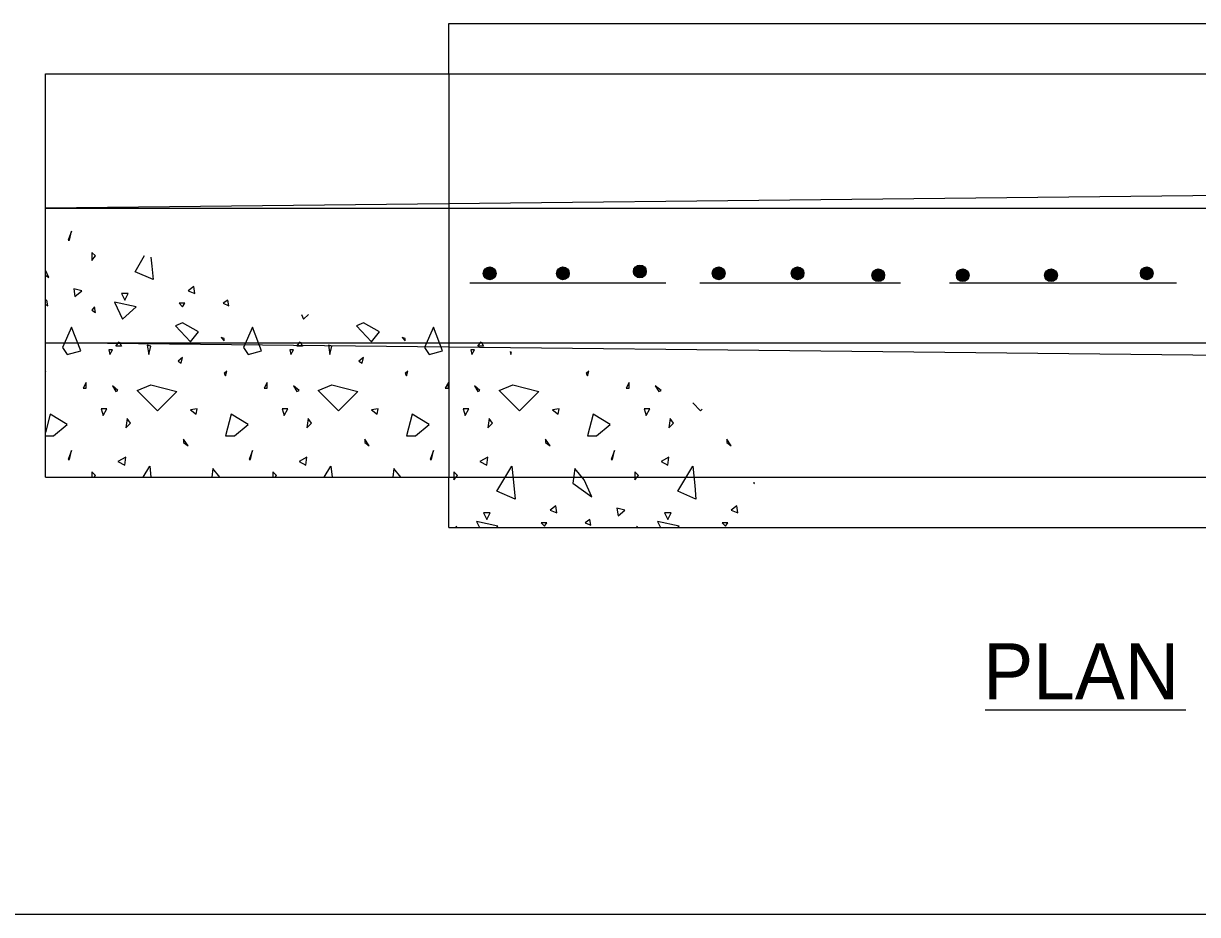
# Model space of a CAD drawing. Extents: x -0.8 to 6.5, y 10.6 to 20.8.
# Drawn here: x 2.206 to 4.302, y 19.16 to 20.751 of the extents above; entities that cross this region are included whole.
import ezdxf

# ---------------------------------------------------------------- set-up
doc = ezdxf.new("R2010")
doc.units = 0
for name, color, linetype in [('DETL-DIMS', 7, 'Continuous'), ('DETL-LINE', 7, 'Continuous'), ('DETL-PATT', 7, 'Continuous'), ('DETL-TITL', 7, 'Continuous')]:
    doc.layers.add(name, color=color, linetype=linetype)

msp = doc.modelspace()

# ---------------------------------------------------------------- linework, layer by layer
at = {"layer": 'DETL-DIMS'}
msp.add_line((5.9505, 19.1603), (0.6594, 19.1603), dxfattribs=at)
at = {"layer": 'DETL-LINE'}
for p, q in [((2.9657, 20.6609), (2.9657, 20.7509)), ((2.9657, 20.7509), (5.3675, 20.7509)), ((2.2458, 19.9408), (2.2458, 20.6609)), ((2.2458, 20.6609), (5.3658, 20.6609)), ((2.9657, 20.6609), (2.9657, 19.9408)), ((5.0074, 20.4509), (2.2458, 20.4209)), ((2.2458, 20.4209), (5.0074, 20.4209)), ((3.003, 20.2881), (3.3531, 20.2881)), ((3.4135, 20.2881), (3.7719, 20.2881)), ((3.8591, 20.2881), (4.2645, 20.2881)), ((2.2458, 20.181), (5.0074, 20.181)), ((5.0074, 20.151), (2.2458, 20.181)), ((2.2458, 19.9408), (5.3658, 19.9408)), ((2.9657, 19.8509), (2.9657, 19.9408)), ((2.9657, 19.8509), (5.3675, 19.8509))]:
    msp.add_line(p, q, dxfattribs=at)
for centre, radius in [((3.0385, 20.3048), 0.0114), ((3.0384, 20.3049), 0.0107), ((3.0373, 20.3049), 0.00926), ((3.0385, 20.3047), 0.0103), ((3.0388, 20.3042), 0.0101), ((3.0388, 20.3045), 0.0094), ((3.039, 20.3045), 0.00889), ((3.0377, 20.3054), 0.00766), ((3.0391, 20.3042), 0.00843), ((3.0375, 20.3045), 0.00665), ((3.0392, 20.3041), 0.00805), ((3.0391, 20.3039), 0.00767), ((3.037, 20.3041), 0.00531), ((3.0393, 20.3039), 0.00747), ((3.0391, 20.304), 0.00722), ((3.0395, 20.3038), 0.0069), ((3.0395, 20.304), 0.00646), ((3.0396, 20.304), 0.00601), ((3.0379, 20.3043), 0.00429), ((3.0396, 20.3042), 0.00551), ((3.0397, 20.304), 0.00519), ((3.0397, 20.304), 0.00468), ((3.0399, 20.3036), 0.00448), ((3.04, 20.3035), 0.00409), ((3.04, 20.3036), 0.00358), ((3.0401, 20.3037), 0.00346), ((3.0401, 20.3034), 0.00319), ((3.0402, 20.3036), 0.00306), ((3.0403, 20.3036), 0.00262), ((3.0401, 20.3038), 0.00218), ((3.0404, 20.3035), 0.00194), ((3.0404, 20.3035), 0.00161), ((3.0406, 20.3034), 0.00123), ((3.0406, 20.3036), 0.00108), ((3.0409, 20.3035), 0.00136), ((3.0405, 20.3036), 0.000706), ((3.1692, 20.3048), 0.0114), ((3.1691, 20.3049), 0.0107), ((3.168, 20.3049), 0.00926), ((3.1692, 20.3047), 0.0103), ((3.1695, 20.3042), 0.0101), ((3.1694, 20.3045), 0.0094), ((3.1684, 20.3054), 0.00766), ((3.1697, 20.3045), 0.00889), ((3.1698, 20.3042), 0.00843), ((3.1682, 20.3045), 0.00665), ((3.1699, 20.3041), 0.00805), ((3.1698, 20.3039), 0.00767), ((3.1677, 20.3041), 0.00531), ((3.17, 20.3039), 0.00747), ((3.1698, 20.304), 0.00722), ((3.1701, 20.3038), 0.0069), ((3.1702, 20.304), 0.00646), ((3.1703, 20.304), 0.00601), ((3.1685, 20.3043), 0.00429), ((3.1703, 20.3042), 0.00551), ((3.1703, 20.304), 0.00519), ((3.1703, 20.304), 0.00468), ((3.1705, 20.3036), 0.00448), ((3.1706, 20.3035), 0.00409), ((3.1706, 20.3036), 0.00358), ((3.1708, 20.3037), 0.00346), ((3.1708, 20.3034), 0.00319), ((3.1709, 20.3036), 0.00306), ((3.171, 20.3036), 0.00262), ((3.1708, 20.3038), 0.00218), ((3.171, 20.3035), 0.00194), ((3.1711, 20.3035), 0.00161), ((3.1712, 20.3034), 0.00123), ((3.1712, 20.3036), 0.00108), ((3.1716, 20.3035), 0.00136), ((3.1712, 20.3036), 0.000706), ((3.3065, 20.3082), 0.0114), ((3.3064, 20.3083), 0.0107), ((3.3054, 20.3083), 0.00926), ((3.3065, 20.308), 0.0103), ((3.3068, 20.3075), 0.0101), ((3.3068, 20.3079), 0.0094), ((3.3058, 20.3087), 0.00766), ((3.307, 20.3078), 0.00889), ((3.3071, 20.3076), 0.00843), ((3.3056, 20.3078), 0.00665), ((3.3072, 20.3075), 0.00805), ((3.3071, 20.3073), 0.00767), ((3.305, 20.3075), 0.00531), ((3.3073, 20.3073), 0.00747), ((3.3072, 20.3074), 0.00722), ((3.3075, 20.3072), 0.0069), ((3.3076, 20.3073), 0.00646), ((3.3076, 20.3074), 0.00601), ((3.3059, 20.3077), 0.00429), ((3.3076, 20.3075), 0.00551), ((3.3077, 20.3074), 0.00519), ((3.3077, 20.3073), 0.00468), ((3.3079, 20.3069), 0.00448), ((3.308, 20.3069), 0.00409), ((3.308, 20.307), 0.00358), ((3.3081, 20.3071), 0.00346), ((3.3081, 20.3068), 0.00319), ((3.3083, 20.307), 0.00306), ((3.3083, 20.3069), 0.00262), ((3.3081, 20.3071), 0.00218), ((3.3084, 20.3069), 0.00194), ((3.3085, 20.3069), 0.00161), ((3.3086, 20.3068), 0.00123), ((3.3086, 20.3069), 0.00108), ((3.309, 20.3069), 0.00136), ((3.3086, 20.3069), 0.000706), ((3.3084, 20.3069), 0.000332), ((3.3087, 20.3069), 0.000211), ((3.4472, 20.3049), 0.0114), ((3.4471, 20.305), 0.0107), ((3.4461, 20.305), 0.00926), ((3.4473, 20.3047), 0.0103), ((3.4476, 20.3042), 0.0101), ((3.4475, 20.3046), 0.0094), ((3.4465, 20.3054), 0.00766), ((3.4478, 20.3045), 0.00889), ((3.4478, 20.3043), 0.00843), ((3.4463, 20.3045), 0.00665), ((3.448, 20.3041), 0.00805), ((3.4478, 20.3039), 0.00767), ((3.4457, 20.3041), 0.00531), ((3.448, 20.3039), 0.00747), ((3.4479, 20.3041), 0.00722), ((3.4482, 20.3039), 0.0069), ((3.4483, 20.304), 0.00646), ((3.4483, 20.3041), 0.00601), ((3.4466, 20.3044), 0.00429), ((3.4483, 20.3042), 0.00551), ((3.4484, 20.3041), 0.00519), ((3.4484, 20.304), 0.00468), ((3.4486, 20.3036), 0.00448), ((3.4487, 20.3036), 0.00409), ((3.4487, 20.3037), 0.00358), ((3.4489, 20.3038), 0.00346), ((3.4489, 20.3034), 0.00319), ((3.449, 20.3037), 0.00306), ((3.449, 20.3036), 0.00262), ((3.4489, 20.3038), 0.00218), ((3.4491, 20.3035), 0.00194), ((3.4492, 20.3036), 0.00161), ((3.4493, 20.3035), 0.00123), ((3.4493, 20.3036), 0.00108), ((3.4497, 20.3036), 0.00136), ((3.4493, 20.3036), 0.000706), ((3.588, 20.3049), 0.0114), ((3.5879, 20.305), 0.0107), ((3.5868, 20.305), 0.00926), ((3.588, 20.3047), 0.0103), ((3.5883, 20.3042), 0.0101), ((3.5882, 20.3046), 0.0094), ((3.5872, 20.3054), 0.00766), ((3.5885, 20.3045), 0.00889), ((3.5886, 20.3043), 0.00843), ((3.587, 20.3045), 0.00665), ((3.5887, 20.3041), 0.00805), ((3.5886, 20.3039), 0.00767), ((3.5865, 20.3041), 0.00531), ((3.5888, 20.3039), 0.00747), ((3.5886, 20.3041), 0.00722), ((3.5889, 20.3039), 0.0069), ((3.589, 20.304), 0.00646), ((3.5873, 20.3044), 0.00429), ((3.5891, 20.3041), 0.00601), ((3.5891, 20.3042), 0.00551), ((3.5891, 20.3041), 0.00519), ((3.5891, 20.304), 0.00468), ((3.5893, 20.3036), 0.00448), ((3.5894, 20.3036), 0.00409), ((3.5894, 20.3037), 0.00358), ((3.5896, 20.3038), 0.00346), ((3.5896, 20.3034), 0.00319), ((3.5897, 20.3037), 0.00306), ((3.5898, 20.3036), 0.00262), ((3.5896, 20.3038), 0.00218), ((3.5898, 20.3035), 0.00194), ((3.5899, 20.3036), 0.00161), ((3.59, 20.3035), 0.00123), ((3.59, 20.3036), 0.00108), ((3.5904, 20.3036), 0.00136), ((3.59, 20.3036), 0.000706), ((3.732, 20.3015), 0.0114), ((3.7319, 20.3016), 0.0107), ((3.7309, 20.3016), 0.00926), ((3.7321, 20.3013), 0.0103), ((3.7324, 20.3008), 0.0101), ((3.7323, 20.3012), 0.0094), ((3.7313, 20.3021), 0.00766), ((3.7326, 20.3012), 0.00889), ((3.7326, 20.3009), 0.00843), ((3.7311, 20.3012), 0.00665), ((3.7328, 20.3008), 0.00805), ((3.7326, 20.3006), 0.00767), ((3.7305, 20.3008), 0.00531), ((3.7328, 20.3006), 0.00747), ((3.7327, 20.3007), 0.00722), ((3.733, 20.3005), 0.0069), ((3.7331, 20.3006), 0.00646), ((3.7331, 20.3007), 0.00601), ((3.7314, 20.301), 0.00429), ((3.7331, 20.3008), 0.00551), ((3.7332, 20.3007), 0.00519), ((3.7332, 20.3006), 0.00468), ((3.7334, 20.3003), 0.00448), ((3.7335, 20.3002), 0.00409), ((3.8828, 20.3015), 0.0114), ((3.8827, 20.3016), 0.0107), ((3.8817, 20.3016), 0.00926), ((3.8829, 20.3013), 0.0103), ((3.8832, 20.3008), 0.0101), ((3.8831, 20.3012), 0.0094), ((3.8821, 20.3021), 0.00766), ((3.8834, 20.3012), 0.00889), ((3.8834, 20.3009), 0.00843), ((3.8819, 20.3012), 0.00665), ((3.8836, 20.3008), 0.00805), ((3.8834, 20.3006), 0.00767), ((3.8813, 20.3008), 0.00531), ((3.8836, 20.3006), 0.00747), ((3.8835, 20.3007), 0.00722), ((3.8838, 20.3005), 0.0069), ((3.8839, 20.3006), 0.00646), ((3.8839, 20.3007), 0.00601), ((3.8822, 20.301), 0.00429), ((3.8839, 20.3008), 0.00551), ((3.884, 20.3007), 0.00519), ((3.884, 20.3006), 0.00468), ((3.8842, 20.3003), 0.00448), ((3.8843, 20.3002), 0.00409), ((4.0403, 20.3015), 0.0114), ((4.0402, 20.3016), 0.0107), ((4.0392, 20.3016), 0.00926), ((4.0403, 20.3013), 0.0103), ((4.0406, 20.3008), 0.0101), ((4.0406, 20.3012), 0.0094), ((4.0396, 20.3021), 0.00766), ((4.0408, 20.3012), 0.00889), ((4.0409, 20.3009), 0.00843), ((4.0394, 20.3012), 0.00665), ((4.041, 20.3008), 0.00805), ((4.0409, 20.3006), 0.00767), ((4.0388, 20.3008), 0.00531), ((4.0411, 20.3006), 0.00747), ((4.041, 20.3007), 0.00722), ((4.0413, 20.3005), 0.0069), ((4.0414, 20.3006), 0.00646), ((4.0414, 20.3007), 0.00601), ((4.0397, 20.301), 0.00429), ((4.0414, 20.3008), 0.00551), ((4.0415, 20.3007), 0.00519), ((4.0415, 20.3006), 0.00468), ((4.0417, 20.3003), 0.00448), ((4.0418, 20.3002), 0.00409), ((4.2112, 20.3049), 0.0114), ((4.2111, 20.305), 0.0107), ((4.2101, 20.305), 0.00926), ((4.2112, 20.3047), 0.0103), ((4.2115, 20.3042), 0.0101), ((4.2115, 20.3046), 0.0094), ((4.2117, 20.3045), 0.00889), ((4.2104, 20.3054), 0.00766), ((4.2118, 20.3043), 0.00843), ((4.2103, 20.3045), 0.00665), ((4.2119, 20.3041), 0.00805), ((4.2118, 20.3039), 0.00767), ((4.2097, 20.3041), 0.00531), ((4.212, 20.3039), 0.00747), ((4.2119, 20.3041), 0.00722), ((4.2122, 20.3039), 0.0069), ((4.2122, 20.304), 0.00646), ((4.2123, 20.3041), 0.00601), ((4.2106, 20.3044), 0.00429), ((4.2123, 20.3042), 0.00551), ((4.2124, 20.3041), 0.00519), ((4.2124, 20.304), 0.00468), ((4.2126, 20.3036), 0.00448), ((4.2127, 20.3036), 0.00409), ((4.2127, 20.3037), 0.00358), ((4.2128, 20.3038), 0.00346), ((4.2128, 20.3034), 0.00319), ((4.213, 20.3037), 0.00306), ((4.213, 20.3036), 0.00262), ((4.2128, 20.3038), 0.00218), ((4.2131, 20.3035), 0.00194), ((4.2131, 20.3036), 0.00161), ((4.2133, 20.3035), 0.00123), ((4.2133, 20.3036), 0.00108), ((4.2137, 20.3036), 0.00136), ((4.2133, 20.3036), 0.000706), ((3.0404, 20.3036), 0.000332), ((3.0407, 20.3036), 0.000211), ((3.1711, 20.3036), 0.000332), ((3.1714, 20.3036), 0.000211), ((3.4492, 20.3036), 0.000332), ((3.4494, 20.3036), 0.000211), ((3.5899, 20.3036), 0.000332), ((3.5902, 20.3036), 0.000211), ((3.7335, 20.3003), 0.00358), ((3.7337, 20.3004), 0.00346), ((3.7337, 20.3001), 0.00319), ((3.7338, 20.3003), 0.00306), ((3.7338, 20.3003), 0.00262), ((3.7337, 20.3005), 0.00218), ((3.7339, 20.3002), 0.00194), ((3.734, 20.3002), 0.00161), ((3.7341, 20.3001), 0.00123), ((3.7341, 20.3003), 0.00108), ((3.7345, 20.3002), 0.00136), ((3.7341, 20.3003), 0.000706), ((3.734, 20.3003), 0.000332), ((3.7342, 20.3003), 0.000211), ((3.8843, 20.3003), 0.00358), ((3.8845, 20.3004), 0.00346), ((3.8845, 20.3001), 0.00319), ((3.8846, 20.3003), 0.00306), ((3.8846, 20.3003), 0.00262), ((3.8845, 20.3005), 0.00218), ((3.8847, 20.3002), 0.00194), ((3.8848, 20.3002), 0.00161), ((3.8849, 20.3001), 0.00123), ((3.8849, 20.3003), 0.00108), ((3.8853, 20.3002), 0.00136), ((3.8849, 20.3003), 0.000706), ((3.8848, 20.3003), 0.000332), ((3.885, 20.3003), 0.000211), ((4.0418, 20.3003), 0.00358), ((4.0419, 20.3004), 0.00346), ((4.0419, 20.3001), 0.00319), ((4.0421, 20.3003), 0.00306), ((4.0421, 20.3003), 0.00262), ((4.0419, 20.3005), 0.00218), ((4.0422, 20.3002), 0.00194), ((4.0423, 20.3002), 0.00161), ((4.0424, 20.3001), 0.00123), ((4.0424, 20.3003), 0.00108), ((4.0428, 20.3002), 0.00136), ((4.0424, 20.3003), 0.000706), ((4.0423, 20.3003), 0.000332), ((4.0425, 20.3003), 0.000211), ((4.2131, 20.3036), 0.000332), ((4.2134, 20.3036), 0.000211)]:
    msp.add_circle(centre, radius, dxfattribs=at)
at = {"layer": 'DETL-PATT'}
for points in [[(2.2921, 20.3803), (2.2863, 20.3643), (2.2883, 20.3643), (2.2921, 20.3803)], [(2.4339, 20.3336), (2.4356, 20.3176), (2.4376, 20.2936), (2.4055, 20.3076), (2.4226, 20.3366)], [(2.2458, 20.3018), (2.2518, 20.2975), (2.2458, 20.3106)], [(2.2458, 20.249), (2.25, 20.2471), (2.248, 20.2571), (2.2458, 20.2556)], [(2.7024, 20.2315), (2.7064, 20.2231), (2.7154, 20.2313)], [(3.0752, 20.1656), (3.076, 20.1601), (3.0772, 20.1646)], [(2.2458, 20.1286), (2.246, 20.13), (2.2458, 20.1296)], [(3.2152, 20.13), (3.2108, 20.1261), (3.2133, 20.1218), (3.2152, 20.13)], [(2.2458, 20.0148), (2.26, 20.0148), (2.2845, 20.0353), (2.2541, 20.0532), (2.2458, 20.0208)], [(3.418, 20.0625), (3.4148, 20.0593), (3.4008, 20.0735)], [(2.3323, 19.9408), (2.3348, 19.9442), (2.3286, 19.9505), (2.3286, 19.9408)], [(2.4203, 19.9408), (2.4318, 19.9605), (2.4339, 19.9408)], [(2.5571, 19.9408), (2.5446, 19.9562), (2.5424, 19.9408)], [(2.6554, 19.9408), (2.6579, 19.9442), (2.6516, 19.9505), (2.6516, 19.9408)], [(2.7432, 19.9408), (2.7549, 19.9605), (2.7571, 19.9408)], [(2.88, 19.9408), (2.8677, 19.9562), (2.8654, 19.9408)], [(3.5101, 19.9322), (3.5099, 19.9303), (3.5111, 19.9293)], [(2.9795, 19.8509), (2.979, 19.8535), (2.9772, 19.8509)], [(3.0507, 19.8509), (3.0533, 19.8535), (3.015, 19.8617), (3.0202, 19.8509)], [(3.3025, 19.8509), (3.302, 19.8535), (3.3003, 19.8509)], [(3.3736, 19.8509), (3.3765, 19.8535), (3.3381, 19.8617), (3.3431, 19.8509)]]:
    msp.add_lwpolyline(points, dxfattribs=at)
for points in [[(2.3286, 20.3421), (2.3286, 20.3278), (2.3348, 20.3359)], [(2.2965, 20.2773), (2.2983, 20.2635), (2.3103, 20.2735)], [(2.3815, 20.2691), (2.3871, 20.2571), (2.3935, 20.2691)], [(2.5106, 20.2816), (2.5004, 20.2735), (2.5124, 20.2691)], [(2.3286, 20.239), (2.3348, 20.2351), (2.333, 20.2451)], [(2.369, 20.2533), (2.3833, 20.2231), (2.4073, 20.2451)], [(2.4841, 20.2515), (2.4904, 20.2451), (2.4943, 20.2515)], [(2.5629, 20.2515), (2.5729, 20.2471), (2.5711, 20.2571)], [(2.2845, 20.1601), (2.3085, 20.1665), (2.2921, 20.2086), (2.2763, 20.1726)], [(2.4779, 20.2111), (2.5043, 20.1828), (2.5188, 20.2005), (2.4904, 20.2168)], [(2.6074, 20.1601), (2.6314, 20.1665), (2.6153, 20.2086), (2.5993, 20.1726)], [(2.8009, 20.2111), (2.8274, 20.1828), (2.8417, 20.2005), (2.8134, 20.2168)], [(2.9305, 20.1601), (2.9545, 20.1665), (2.9382, 20.2086), (2.9224, 20.1726)], [(2.3771, 20.1828), (2.3815, 20.1746), (2.3713, 20.1746)], [(2.5648, 20.1885), (2.5591, 20.1905), (2.5648, 20.1846)], [(2.7001, 20.1828), (2.7044, 20.1746), (2.6944, 20.1746)], [(2.8879, 20.1885), (2.882, 20.1905), (2.8879, 20.1846)], [(3.0232, 20.1828), (3.0275, 20.1746), (3.0174, 20.1746)], [(2.3588, 20.1683), (2.3608, 20.1601), (2.3651, 20.1683)], [(2.4274, 20.1765), (2.4299, 20.1601), (2.4338, 20.1746)], [(2.6819, 20.1683), (2.6837, 20.1601), (2.6881, 20.1683)], [(2.7506, 20.1765), (2.7529, 20.1601), (2.7567, 20.1746)], [(3.0049, 20.1683), (3.0069, 20.1601), (3.0112, 20.1683)], [(2.4823, 20.1481), (2.4879, 20.1443), (2.4904, 20.1545)], [(2.8052, 20.1481), (2.8111, 20.1443), (2.8134, 20.1545)], [(2.5691, 20.13), (2.5648, 20.1261), (2.5671, 20.1218)], [(2.8922, 20.13), (2.8879, 20.1261), (2.8902, 20.1218)], [(2.3185, 20.1098), (2.3128, 20.0997), (2.3185, 20.0997)], [(2.3713, 20.094), (2.3751, 20.0958), (2.3651, 20.104)], [(2.4338, 20.106), (2.4803, 20.094), (2.4458, 20.0593), (2.4093, 20.0958)], [(2.6416, 20.1098), (2.6357, 20.0997), (2.6416, 20.0997)], [(2.6944, 20.094), (2.6982, 20.0958), (2.6881, 20.104)], [(2.7567, 20.106), (2.8034, 20.094), (2.7687, 20.0593), (2.7322, 20.0958)], [(2.9647, 20.1098), (2.9589, 20.0997), (2.9647, 20.0997)], [(3.0174, 20.094), (3.0212, 20.0958), (3.0112, 20.104)], [(3.0798, 20.106), (3.1263, 20.094), (3.0918, 20.0593), (3.0553, 20.0958)], [(3.2876, 20.1098), (3.282, 20.0997), (3.2876, 20.0997)], [(3.3405, 20.094), (3.3443, 20.0958), (3.3341, 20.104)], [(2.345, 20.0632), (2.3488, 20.0512), (2.355, 20.0632)], [(2.5043, 20.0613), (2.5144, 20.0532), (2.5163, 20.0632)], [(2.5831, 20.0148), (2.6074, 20.0353), (2.5773, 20.0532), (2.5671, 20.0148)], [(2.6679, 20.0632), (2.6717, 20.0512), (2.6781, 20.0632)], [(2.8274, 20.0613), (2.8374, 20.0532), (2.8394, 20.0632)], [(2.906, 20.0148), (2.9305, 20.0353), (2.9004, 20.0532), (2.8902, 20.0148)], [(2.991, 20.0632), (2.9949, 20.0512), (3.001, 20.0632)], [(3.1503, 20.0613), (3.1605, 20.0532), (3.1623, 20.0632)], [(3.2292, 20.0148), (3.2537, 20.0353), (3.2233, 20.0532), (3.2133, 20.0148)], [(3.314, 20.0632), (3.318, 20.0512), (3.3241, 20.0632)], [(2.3915, 20.0455), (2.3891, 20.0292), (2.3973, 20.0373)], [(2.7146, 20.0455), (2.7121, 20.0292), (2.7202, 20.0373)], [(3.0375, 20.0455), (3.0352, 20.0292), (3.0434, 20.0373)], [(3.3606, 20.0455), (3.3581, 20.0292), (3.3663, 20.0373)], [(2.4923, 20.009), (2.4923, 20.0028), (2.5004, 19.997)], [(2.8154, 20.009), (2.8154, 20.0028), (2.8236, 19.997)], [(3.1383, 20.009), (3.1383, 20.0028), (3.1465, 19.997)], [(3.4615, 20.009), (3.4615, 20.0028), (3.4696, 19.997)], [(2.2863, 19.9725), (2.2883, 19.9725), (2.2921, 19.9888)], [(2.3751, 19.9687), (2.3871, 19.9625), (2.3891, 19.9768)], [(2.6094, 19.9725), (2.6114, 19.9725), (2.6153, 19.9888)], [(2.6982, 19.9687), (2.7102, 19.9625), (2.7121, 19.9768)], [(2.9325, 19.9725), (2.9344, 19.9725), (2.9382, 19.9888)], [(3.0212, 19.9687), (3.0332, 19.9625), (3.0352, 19.9768)], [(3.2555, 19.9725), (3.2575, 19.9725), (3.2613, 19.9888)], [(3.3443, 19.9687), (3.3563, 19.9625), (3.3581, 19.9768)], [(2.9747, 19.9505), (2.9747, 19.936), (2.9809, 19.9442)], [(3.0817, 19.926), (3.0837, 19.902), (3.0515, 19.9158), (3.0778, 19.9605)], [(3.1907, 19.9562), (3.1868, 19.9303), (3.221, 19.9058), (3.207, 19.936)], [(3.2978, 19.9505), (3.2978, 19.936), (3.304, 19.9442)], [(3.4048, 19.926), (3.4066, 19.902), (3.3745, 19.9158), (3.401, 19.9605)], [(3.1567, 19.89), (3.1465, 19.8819), (3.1585, 19.8775)], [(3.2656, 19.8857), (3.2675, 19.8717), (3.2795, 19.8819)], [(3.4796, 19.89), (3.4696, 19.8819), (3.4816, 19.8775)], [(3.0275, 19.8775), (3.0332, 19.8655), (3.0395, 19.8775)], [(3.209, 19.8597), (3.219, 19.8554), (3.2172, 19.8655)], [(3.3505, 19.8775), (3.3563, 19.8655), (3.3625, 19.8775)], [(3.1302, 19.8597), (3.1365, 19.8535), (3.1403, 19.8597)], [(3.4533, 19.8597), (3.4595, 19.8535), (3.4633, 19.8597)]]:
    msp.add_lwpolyline(points, close=True, dxfattribs=at)
at = {"layer": 'DETL-TITL'}
msp.add_line((3.9227, 19.5259), (4.281, 19.5259), dxfattribs=at)

# ---------------------------------------------------------------- texts
msp.add_text('PLAN', height=0.09998, dxfattribs=at).set_placement((3.9194, 19.5443))

doc.saveas('drawing.dxf')
